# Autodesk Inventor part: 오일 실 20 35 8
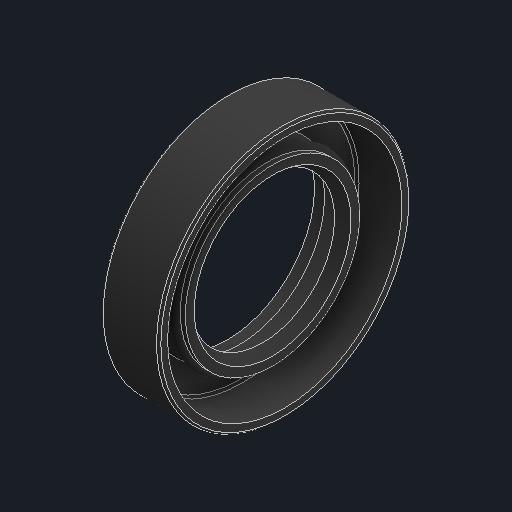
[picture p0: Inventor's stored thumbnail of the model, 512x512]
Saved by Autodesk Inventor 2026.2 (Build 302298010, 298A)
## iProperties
Created: 2026-03
Part Number: 오일 실 20 35 8
Material: 고무
Description: 오일-실
Document SubType Name: Modeling
Designer: PC2-02
Density: 0.93 g/cm^3
Appearance: 기본값
Author: jhkim
Sending System: Autodesk Inventor 2026
Preprocessor: ST-DEVELOPER v20.1
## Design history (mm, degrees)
feature "Solid1"
node "솔리드1"
